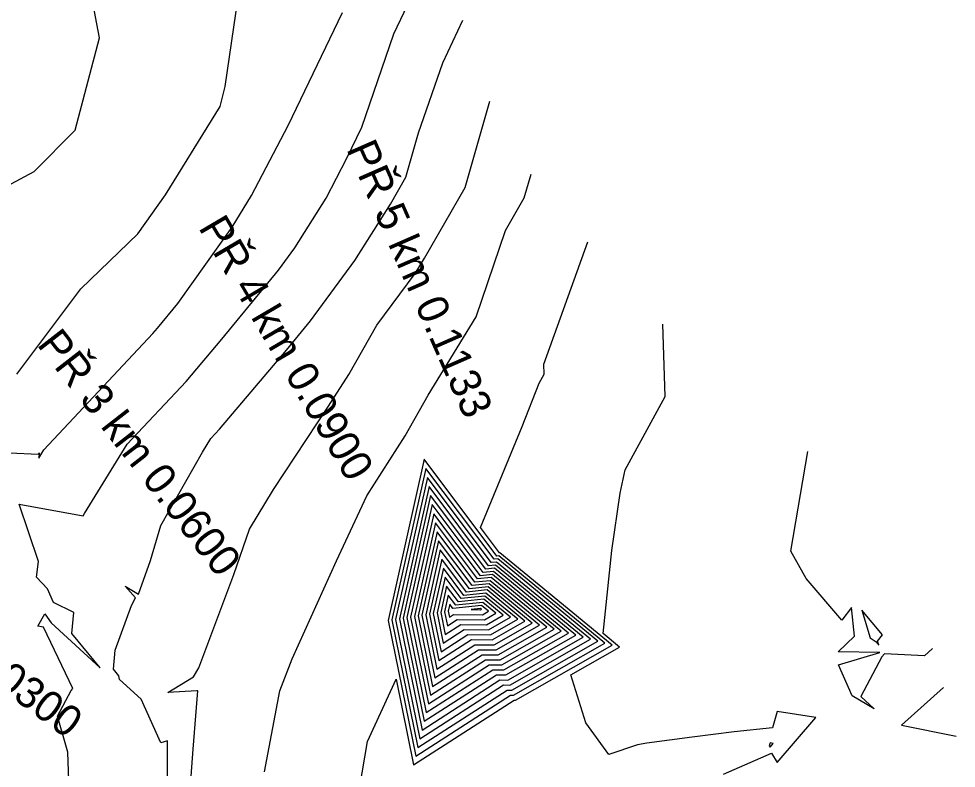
# Model space of a CAD drawing. Extents: x -549394 to -546608, y -1037055 to -1033629.
# Drawn here: x -547499.1 to -547224.8, y -1035194.8 to -1034975.5 of the extents above; entities that cross this region are included whole.
import ezdxf

# ---------------------------------------------------------------- set-up
doc = ezdxf.new("R2010")
doc.units = 0
for name, color, linetype in [('hlavni_vrst', 7, 'Continuous'), ('norm_vrst', 7, 'Continuous'), ('x_popis_pricne_rezy_C141', 7, 'Continuous')]:
    doc.layers.add(name, color=color, linetype=linetype)

msp = doc.modelspace()

# ---------------------------------------------------------------- linework, layer by layer
at = {"layer": 'hlavni_vrst'}
for p, q in [((-547389.33, -1034979.93), (-547375.98, -1034951.49)), ((-547398.7, -1035007.27), (-547389.33, -1034979.93)), ((-547403.08, -1035016.36), (-547398.7, -1035007.27)), ((-547409.12, -1035027.98), (-547403.08, -1035016.36)), ((-547418.29, -1035042.55), (-547409.12, -1035027.98)), ((-547423.11, -1035049.09), (-547418.29, -1035042.55)), ((-547439.63, -1035069.29), (-547423.11, -1035049.09)), ((-547309.93, -1035086.01), (-547310.62, -1035064.9)), ((-547450.13, -1035081.66), (-547439.63, -1035069.29)), ((-547467.32, -1035100.01), (-547450.13, -1035081.66)), ((-547321.67, -1035107.49), (-547309.93, -1035086.01)), ((-547479.83, -1035120.29), (-547467.32, -1035100.01)), ((-547323.09, -1035114.37), (-547321.67, -1035107.49)), ((-547379.06, -1035112.39), (-547387.73, -1035151.11)), ((-547361.64, -1035135.62), (-547379.06, -1035112.39)), ((-547325.62, -1035131.12), (-547323.09, -1035114.37)), ((-547498.94, -1035117.55), (-547498.94, -1035117.55)), ((-547498.94, -1035117.55), (-547498.94, -1035117.55)), ((-547498.94, -1035117.55), (-547498.94, -1035117.55)), ((-547498.94, -1035117.55), (-547480.25, -1035121.02)), ((-547498.94, -1035117.55), (-547498.94, -1035117.55)), ((-547493.26, -1035134.32), (-547498.94, -1035117.55)), ((-547498.94, -1035117.55), (-547498.94, -1035117.55)), ((-547498.94, -1035117.55), (-547498.94, -1035117.55)), ((-547498.94, -1035117.55), (-547498.94, -1035117.55)), ((-547480.25, -1035121.02), (-547479.83, -1035120.29)), ((-547376.72, -1035125.65), (-547382.23, -1035150.26)), ((-547365.64, -1035140.41), (-547376.72, -1035125.65)), ((-547328.15, -1035155.42), (-547325.62, -1035131.12)), ((-547493.87, -1035138.92), (-547493.26, -1035134.32)), ((-547359.58, -1035135.41), (-547361.64, -1035135.62)), ((-547333.98, -1035156.47), (-547359.58, -1035135.41)), ((-547490.66, -1035142.33), (-547493.87, -1035138.92)), ((-547374.37, -1035138.91), (-547376.72, -1035149.41)), ((-547369.65, -1035145.21), (-547374.37, -1035138.91)), ((-547361.15, -1035139.95), (-547365.64, -1035140.41)), ((-547344.61, -1035153.56), (-547361.15, -1035139.95)), ((-547488.93, -1035146.33), (-547490.66, -1035142.33)), ((-547482.97, -1035149.28), (-547488.93, -1035146.33)), ((-547362.72, -1035144.5), (-547369.65, -1035145.21)), ((-547355.24, -1035150.65), (-547362.72, -1035144.5)), ((-547493.51, -1035153.28), (-547491.47, -1035149.64)), ((-547491.47, -1035149.64), (-547489.56, -1035152.3)), ((-547483.54, -1035155.44), (-547482.97, -1035149.28)), ((-547376.72, -1035149.41), (-547374.92, -1035158.24)), ((-547489.56, -1035152.3), (-547475.31, -1035165.43)), ((-547387.73, -1035151.11), (-547381.09, -1035183.66)), ((-547382.23, -1035150.26), (-547378.01, -1035170.95)), ((-547361.68, -1035154.32), (-547355.24, -1035150.65)), ((-547491.88, -1035153.58), (-547493.51, -1035153.28)), ((-547483.29, -1035171.5), (-547491.88, -1035153.58)), ((-547374.92, -1035158.24), (-547368.75, -1035154.26)), ((-547368.75, -1035154.26), (-547361.68, -1035154.32)), ((-547358.84, -1035161.67), (-547344.61, -1035153.56)), ((-547475.31, -1035165.43), (-547483.54, -1035155.44)), ((-547356.01, -1035169.02), (-547333.98, -1035156.47)), ((-547323.35, -1035159.37), (-547328.15, -1035155.42)), ((-547337.6, -1035167.5), (-547323.35, -1035159.37)), ((-547378.01, -1035170.95), (-547363.53, -1035161.63)), ((-547363.53, -1035161.63), (-547358.84, -1035161.67)), ((-547381.09, -1035183.66), (-547358.32, -1035169.01)), ((-547358.32, -1035169.01), (-547356.01, -1035169.02)), ((-547333.21, -1035181.55), (-547337.6, -1035167.5)), ((-547483.7, -1035172.06), (-547483.29, -1035171.5)), ((-547228.59, -1035171.26), (-547240.83, -1035182.23)), ((-547487.72, -1035179.56), (-547483.7, -1035172.06)), ((-547484.7, -1035190.12), (-547487.72, -1035179.56)), ((-547277.19, -1035178.24), (-547278.61, -1035182.98)), ((-547277.24, -1035193.14), (-547265.9, -1035179.96)), ((-547265.9, -1035179.96), (-547277.19, -1035178.24)), ((-547326.47, -1035190.83), (-547333.21, -1035181.55)), ((-547240.83, -1035182.23), (-547224.82, -1035185.5)), ((-547289.76, -1035184.18), (-547302.05, -1035185.79)), ((-547278.61, -1035182.98), (-547289.76, -1035184.18)), ((-547318.11, -1035188.02), (-547326.47, -1035190.83)), ((-547315.3, -1035187.46), (-547318.11, -1035188.02)), ((-547302.05, -1035185.79), (-547315.3, -1035187.46)), ((-547483.99, -1035210.2), (-547484.7, -1035190.12)), ((-547292.9, -1035196.54), (-547278.84, -1035190.47)), ((-547278.84, -1035190.47), (-547277.24, -1035193.14))]:
    msp.add_line(p, q, dxfattribs=at)
at = {"layer": 'norm_vrst'}
for p, q in [((-547438.69, -1034995.3), (-547431.24, -1034944.16)), ((-547475.43, -1034981.06), (-547477.76, -1034968.93)), ((-547420.31, -1035006.73), (-547404.38, -1034973.72)), ((-547375.06, -1034988.39), (-547369.21, -1034975.93)), ((-547482.58, -1035008.1), (-547475.43, -1034981.06)), ((-547382.1, -1035008.94), (-547375.06, -1034988.39)), ((-547440.2, -1035001.18), (-547438.69, -1034995.3)), ((-547456.12, -1035027.06), (-547440.2, -1035001.18)), ((-547368.51, -1035024.92), (-547361.28, -1034999.68)), ((-547430.97, -1035027.25), (-547420.31, -1035006.73)), ((-547494.58, -1035020.17), (-547482.58, -1035008.1)), ((-547385.81, -1035021.9), (-547382.1, -1035008.94)), ((-547514.67, -1035031.07), (-547494.58, -1035020.17)), ((-547351.21, -1035027.95), (-547349.22, -1035021)), ((-547390.34, -1035029.8), (-547385.81, -1035021.9)), ((-547380.35, -1035045.58), (-547368.51, -1035024.92)), ((-547464.29, -1035038.5), (-547456.12, -1035027.06)), ((-547436.64, -1035036.48), (-547430.97, -1035027.25)), ((-547356.68, -1035037.5), (-547351.21, -1035027.95)), ((-547400.72, -1035046.29), (-547390.34, -1035029.8)), ((-547452.59, -1035058.81), (-547436.64, -1035036.48)), ((-547480.94, -1035054.58), (-547464.29, -1035038.5)), ((-547365.24, -1035062.74), (-547356.68, -1035037.5)), ((-547345.49, -1035076.61), (-547332.56, -1035040.77)), ((-547383.15, -1035050.04), (-547380.35, -1035045.58)), ((-547413.72, -1035063.93), (-547400.72, -1035046.29)), ((-547394.33, -1035065.22), (-547383.15, -1035050.04)), ((-547499.6, -1035079.52), (-547480.94, -1035054.58)), ((-547458.52, -1035066.05), (-547452.59, -1035058.81)), ((-547420.74, -1035072.52), (-547413.72, -1035063.93)), ((-547379.26, -1035085.64), (-547365.24, -1035062.74)), ((-547459.89, -1035067.67), (-547458.52, -1035066.05)), ((-547402.49, -1035079.59), (-547394.33, -1035065.22)), ((-547491.77, -1035101.71), (-547459.89, -1035067.67)), ((-547440.38, -1035095.64), (-547420.74, -1035072.52)), ((-547345.39, -1035079.55), (-547345.49, -1035076.61)), ((-547408.42, -1035088.9), (-547402.49, -1035079.59)), ((-547346.81, -1035082.13), (-547345.39, -1035079.55)), ((-547351.76, -1035094.86), (-547346.81, -1035082.13)), ((-547386.05, -1035097.61), (-547379.26, -1035085.64)), ((-547424.58, -1035113.3), (-547408.42, -1035088.9)), ((-547363.97, -1035124.4), (-547351.76, -1035094.86)), ((-547442.88, -1035098.31), (-547440.38, -1035095.64)), ((-547397.23, -1035115.14), (-547386.05, -1035097.61)), ((-547445.35, -1035102.31), (-547442.88, -1035098.31)), ((-547501.78, -1035102.57), (-547493.31, -1035102.92)), ((-547493.31, -1035102.92), (-547493.12, -1035102.53)), ((-547493.12, -1035102.53), (-547493.18, -1035104.1)), ((-547493.18, -1035104.1), (-547492.36, -1035102.68)), ((-547492.36, -1035102.68), (-547491.77, -1035101.71)), ((-547457.52, -1035123.77), (-547445.35, -1035102.31)), ((-547273.24, -1035131.36), (-547268.2, -1035102.17)), ((-547380.47, -1035104.44), (-547391.03, -1035151.62)), ((-547359.24, -1035132.74), (-547380.47, -1035104.44)), ((-547380, -1035107.09), (-547389.93, -1035151.45)), ((-547360.04, -1035133.7), (-547380, -1035107.09)), ((-547379.53, -1035109.74), (-547388.83, -1035151.28)), ((-547360.84, -1035134.66), (-547379.53, -1035109.74)), ((-547431.58, -1035124.92), (-547424.58, -1035113.3)), ((-547406.17, -1035134.15), (-547397.23, -1035115.14)), ((-547378.59, -1035115.04), (-547386.63, -1035150.94)), ((-547362.44, -1035136.58), (-547378.59, -1035115.04)), ((-547378.12, -1035117.7), (-547385.53, -1035150.77)), ((-547363.24, -1035137.54), (-547378.12, -1035117.7)), ((-547377.65, -1035120.35), (-547384.43, -1035150.6)), ((-547364.04, -1035138.5), (-547377.65, -1035120.35)), ((-547460.51, -1035134.02), (-547457.52, -1035123.77)), ((-547436.15, -1035138.18), (-547431.58, -1035124.92)), ((-547377.19, -1035123), (-547383.33, -1035150.43)), ((-547364.84, -1035139.46), (-547377.19, -1035123)), ((-547358.43, -1035131.78), (-547363.97, -1035124.4)), ((-547376.25, -1035128.31), (-547381.13, -1035150.09)), ((-547366.45, -1035141.37), (-547376.25, -1035128.31)), ((-547375.78, -1035130.96), (-547380.03, -1035149.92)), ((-547367.25, -1035142.33), (-547375.78, -1035130.96)), ((-547358.64, -1035132.68), (-547359.24, -1035132.74)), ((-547327.6, -1035158.21), (-547358.64, -1035132.68)), ((-547358.32, -1035131.77), (-547358.43, -1035131.78)), ((-547325.47, -1035158.79), (-547358.32, -1035131.77)), ((-547268.74, -1035139.27), (-547273.24, -1035131.36)), ((-547464.01, -1035143.87), (-547460.51, -1035134.02)), ((-547419.09, -1035162.8), (-547406.17, -1035134.15)), ((-547375.31, -1035133.61), (-547378.93, -1035149.75)), ((-547368.05, -1035143.29), (-547375.31, -1035133.61)), ((-547359.27, -1035134.5), (-547360.84, -1035134.66)), ((-547358.95, -1035133.59), (-547360.04, -1035133.7)), ((-547331.85, -1035157.05), (-547359.27, -1035134.5)), ((-547329.72, -1035157.63), (-547358.95, -1035133.59)), ((-547446.37, -1035165.49), (-547436.15, -1035138.18)), ((-547374.84, -1035136.26), (-547377.82, -1035149.58)), ((-547368.85, -1035144.25), (-547374.84, -1035136.26)), ((-547360.52, -1035138.13), (-547364.04, -1035138.5)), ((-547360.21, -1035137.22), (-547363.24, -1035137.54)), ((-547359.89, -1035136.31), (-547362.44, -1035136.58)), ((-547340.36, -1035154.72), (-547360.52, -1035138.13)), ((-547338.23, -1035155.3), (-547360.21, -1035137.22)), ((-547336.1, -1035155.89), (-547359.89, -1035136.31)), ((-547464.91, -1035144.94), (-547467.94, -1035141.53)), ((-547467.94, -1035141.53), (-547464.01, -1035143.87)), ((-547373.9, -1035141.57), (-547375.62, -1035149.24)), ((-547370.45, -1035146.17), (-547373.9, -1035141.57)), ((-547361.46, -1035140.86), (-547366.45, -1035141.37)), ((-547360.84, -1035139.04), (-547364.84, -1035139.46)), ((-547346.73, -1035152.98), (-547361.46, -1035140.86)), ((-547342.48, -1035154.14), (-547360.84, -1035139.04)), ((-547258.3, -1035151.47), (-547268.74, -1035139.27)), ((-547373.44, -1035144.22), (-547374.52, -1035149.07)), ((-547371.25, -1035147.13), (-547373.44, -1035144.22)), ((-547362.41, -1035143.59), (-547368.85, -1035144.25)), ((-547362.09, -1035142.68), (-547368.05, -1035143.29)), ((-547361.78, -1035141.77), (-547367.25, -1035142.33)), ((-547353.11, -1035151.23), (-547362.41, -1035143.59)), ((-547350.99, -1035151.81), (-547362.09, -1035142.68)), ((-547348.86, -1035152.4), (-547361.78, -1035141.77)), ((-547466.11, -1035147.23), (-547464.91, -1035144.94)), ((-547372.97, -1035146.87), (-547373.42, -1035148.9)), ((-547372.05, -1035148.09), (-547372.97, -1035146.87)), ((-547363.35, -1035146.31), (-547371.25, -1035147.13)), ((-547363.04, -1035145.4), (-547370.45, -1035146.17)), ((-547359.49, -1035149.49), (-547363.35, -1035146.31)), ((-547357.37, -1035150.07), (-547363.04, -1035145.4)), ((-547470.9, -1035160.29), (-547466.11, -1035147.23)), ((-547378.93, -1035149.75), (-547376.16, -1035163.32)), ((-547377.82, -1035149.58), (-547375.54, -1035160.78)), ((-547375.62, -1035149.24), (-547374.31, -1035155.69)), ((-547374.52, -1035149.07), (-547373.69, -1035153.15)), ((-547373.42, -1035148.9), (-547373.07, -1035150.61)), ((-547373.07, -1035150.61), (-547371.88, -1035149.84)), ((-547363.66, -1035147.22), (-547372.05, -1035148.09)), ((-547371.88, -1035149.84), (-547363.38, -1035149.91)), ((-547363.98, -1035148.13), (-547366.75, -1035148.42)), ((-547366.75, -1035148.42), (-547363.95, -1035148.44)), ((-547363.74, -1035148.33), (-547363.98, -1035148.13)), ((-547363.95, -1035148.44), (-547363.74, -1035148.33)), ((-547361.62, -1035148.91), (-547363.66, -1035147.22)), ((-547363.38, -1035149.91), (-547361.62, -1035148.91)), ((-547362.81, -1035151.38), (-547359.49, -1035149.49)), ((-547255.46, -1035147.84), (-547258.3, -1035151.47)), ((-547254.54, -1035156.23), (-547255.46, -1035147.84)), ((-547252.45, -1035148.62), (-547249.96, -1035156.67)), ((-547246.37, -1035155.76), (-547252.45, -1035148.62)), ((-547391.03, -1035151.62), (-547382.94, -1035191.28)), ((-547389.93, -1035151.45), (-547382.32, -1035188.74)), ((-547388.83, -1035151.28), (-547381.71, -1035186.2)), ((-547386.63, -1035150.94), (-547380.47, -1035181.11)), ((-547385.53, -1035150.77), (-547379.86, -1035178.57)), ((-547384.43, -1035150.6), (-547379.24, -1035176.03)), ((-547383.33, -1035150.43), (-547378.62, -1035173.49)), ((-547381.13, -1035150.09), (-547377.39, -1035168.4)), ((-547380.03, -1035149.92), (-547376.77, -1035165.86)), ((-547373.69, -1035153.15), (-547370.84, -1035151.32)), ((-547370.84, -1035151.32), (-547362.81, -1035151.38)), ((-547362.24, -1035152.85), (-547357.37, -1035150.07)), ((-547361.11, -1035155.79), (-547353.11, -1035151.23)), ((-547360.54, -1035157.26), (-547350.99, -1035151.81)), ((-547359.98, -1035158.73), (-547348.86, -1035152.4)), ((-547374.31, -1035155.69), (-547369.79, -1035152.79)), ((-547369.79, -1035152.79), (-547362.24, -1035152.85)), ((-547359.41, -1035160.2), (-547346.73, -1035152.98)), ((-547358.27, -1035163.14), (-547342.48, -1035154.14)), ((-547357.71, -1035164.61), (-547340.36, -1035154.72)), ((-547357.14, -1035166.08), (-547338.23, -1035155.3)), ((-547376.16, -1035163.32), (-547366.66, -1035157.21)), ((-547375.54, -1035160.78), (-547367.71, -1035155.74)), ((-547367.71, -1035155.74), (-547361.11, -1035155.79)), ((-547366.66, -1035157.21), (-547360.54, -1035157.26)), ((-547356.57, -1035167.55), (-547336.1, -1035155.89)), ((-547355.44, -1035170.49), (-547331.85, -1035157.05)), ((-547354.87, -1035171.97), (-547329.72, -1035157.63)), ((-547259.33, -1035160.77), (-547254.54, -1035156.23)), ((-547249.96, -1035156.67), (-547248.28, -1035157.82)), ((-547248.28, -1035157.82), (-547247.47, -1035158.85)), ((-547247.82, -1035157.66), (-547246.37, -1035155.76)), ((-547247.47, -1035158.85), (-547247.82, -1035157.66)), ((-547471.41, -1035165.85), (-547470.9, -1035160.29)), ((-547377.39, -1035168.4), (-547364.58, -1035160.16)), ((-547376.77, -1035165.86), (-547365.62, -1035158.69)), ((-547365.62, -1035158.69), (-547359.98, -1035158.73)), ((-547364.58, -1035160.16), (-547359.41, -1035160.2)), ((-547354.3, -1035173.44), (-547327.6, -1035158.21)), ((-547353.74, -1035174.91), (-547325.47, -1035158.79)), ((-547247.17, -1035160.96), (-547259.33, -1035160.77)), ((-547231.76, -1035159.81), (-547234.13, -1035161.94)), ((-547422.74, -1035172.18), (-547419.09, -1035162.8)), ((-547378.62, -1035173.49), (-547362.49, -1035163.11)), ((-547362.49, -1035163.11), (-547358.27, -1035163.14)), ((-547259.27, -1035164.6), (-547247.17, -1035160.96)), ((-547246.61, -1035162.26), (-547252.78, -1035173.87)), ((-547245.84, -1035161.34), (-547246.61, -1035162.26)), ((-547234.13, -1035161.94), (-547245.84, -1035161.34)), ((-547469.79, -1035167.81), (-547471.41, -1035165.85)), ((-547447.91, -1035168.13), (-547446.37, -1035165.49)), ((-547379.86, -1035178.57), (-547360.41, -1035166.06)), ((-547379.24, -1035176.03), (-547361.45, -1035164.58)), ((-547361.45, -1035164.58), (-547357.71, -1035164.61)), ((-547360.41, -1035166.06), (-547357.14, -1035166.08)), ((-547255.27, -1035173.67), (-547259.27, -1035164.6)), ((-547469.59, -1035168.84), (-547469.79, -1035167.81)), ((-547463.25, -1035174.61), (-547469.59, -1035168.84)), ((-547455.5, -1035172.67), (-547447.91, -1035168.13)), ((-547397.01, -1035186.98), (-547388.67, -1035168.78)), ((-547388.67, -1035168.78), (-547383.56, -1035193.82)), ((-547380.47, -1035181.11), (-547359.36, -1035167.53)), ((-547359.36, -1035167.53), (-547356.57, -1035167.55)), ((-547381.71, -1035186.2), (-547357.28, -1035170.48)), ((-547357.28, -1035170.48), (-547355.44, -1035170.49)), ((-547447, -1035172.23), (-547455.5, -1035172.67)), ((-547455.5, -1035172.67), (-547455.5, -1035172.67)), ((-547455.5, -1035172.67), (-547455.5, -1035172.67)), ((-547455.5, -1035172.67), (-547455.5, -1035172.67)), ((-547455.5, -1035172.67), (-547455.5, -1035172.67)), ((-547455.5, -1035172.67), (-547455.5, -1035172.67)), ((-547448.06, -1035189.29), (-547446.65, -1035172.21)), ((-547446.65, -1035172.21), (-547447, -1035172.23)), ((-547427.14, -1035195.86), (-547422.74, -1035172.18)), ((-547382.94, -1035191.28), (-547355.19, -1035173.43)), ((-547382.32, -1035188.74), (-547356.23, -1035171.95)), ((-547356.23, -1035171.95), (-547354.87, -1035171.97)), ((-547355.19, -1035173.43), (-547354.3, -1035173.44)), ((-547248.86, -1035177.5), (-547255.27, -1035173.67)), ((-547252.78, -1035173.87), (-547248.86, -1035177.5)), ((-547457.56, -1035187.43), (-547463.25, -1035174.61)), ((-547383.56, -1035193.82), (-547354.15, -1035174.9)), ((-547354.15, -1035174.9), (-547353.74, -1035174.91)), ((-547455.58, -1035186.85), (-547457.56, -1035187.43)), ((-547455.6, -1035197.85), (-547455.58, -1035186.85)), ((-547399.36, -1035200.76), (-547397.01, -1035186.98)), ((-547279.27, -1035187.44), (-547279.52, -1035188.27)), ((-547279.52, -1035188.27), (-547279.28, -1035188.67)), ((-547279.28, -1035188.67), (-547278.34, -1035187.58)), ((-547278.34, -1035187.58), (-547279.27, -1035187.44)), ((-547448.87, -1035199.84), (-547448.06, -1035189.29))]:
    msp.add_line(p, q, dxfattribs=at)

# ---------------------------------------------------------------- texts
at = {"layer": 'x_popis_pricne_rezy_C141'}
for s, rotation, p in [('PŘ 5 km 0.1133', 293.6926, (-547403.33, -1035013.55)), ('PŘ 4 km 0.0900', 300.4643, (-547446.68, -1035036.62)), ('PŘ 3 km 0.0600', 307.9233, (-547493.98, -1035070.9)), ('PŘ 2 km 0.0300', 323.0982, (-547554.45, -1035134.22))]:
    msp.add_text(s, height=9.0627, rotation=rotation, dxfattribs=at).set_placement(p)

doc.saveas('drawing.dxf')
